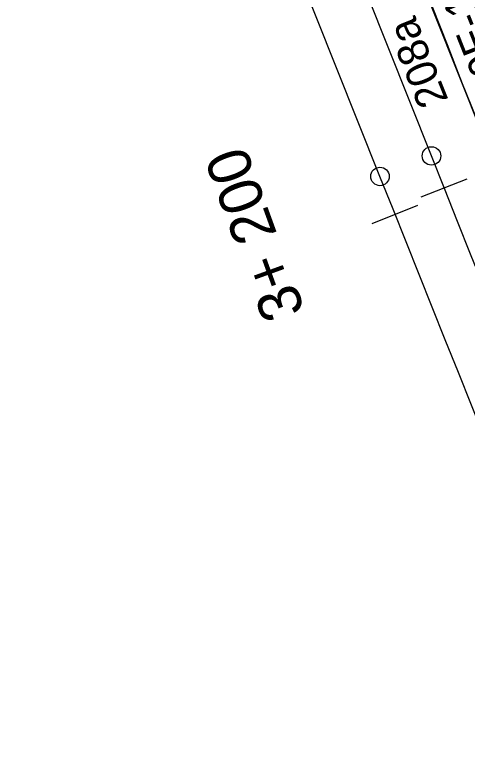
# Model space of a CAD drawing. Extents: x 149855 to 151460, y 6580726 to 6583068.
# Drawn here: x 150983.5 to 151020.2, y 6581433.2 to 6581493.4 of the extents above; entities that cross this region are included whole.
import ezdxf

# ---------------------------------------------------------------- set-up
doc = ezdxf.new("R2010")
doc.units = 0
for name, color, linetype in [('Hektometer L', 7, 'Continuous'), ('Hektometer T', 7, 'Continuous'), ('Spårmitt L', 7, 'Continuous'), ('Tp bef behålls P', 7, 'Continuous'), ('Växel L', 7, 'Continuous'), ('Växelnummer T', 7, 'Continuous'), ('Växeltyp T', 7, 'Continuous')]:
    doc.layers.add(name, color=color, linetype=linetype)

msp = doc.modelspace()

# ---------------------------------------------------------------- linework, layer by layer
at = {"layer": 'Hektometer L'}
for points in [[(151016.511, 6581478.609), (151020.226, 6581480.091)], [(151012.52, 6581476.468), (151016.235, 6581477.95)]]:
    msp.add_lwpolyline(points, dxfattribs=at)
at = {"layer": 'Spårmitt L'}
for points in [[(151021.567, 6581483.477), (150991.892, 6581557.911)], [(151017.336, 6581481.94), (150987.713, 6581556.243)], [(151013.156, 6581480.274), (150983.533, 6581554.575)], [(151037.777, 6581431.651), (151036.669, 6581434.284), (151035.565, 6581436.92), (151034.467, 6581439.558), (151033.373, 6581442.197), (151032.284, 6581444.838), (151031.199, 6581447.482), (151030.118, 6581450.126), (151029.04, 6581452.772), (151027.966, 6581455.42), (151026.895, 6581458.068), (151025.826, 6581460.718), (151024.759, 6581463.369), (151023.695, 6581466.02), (151022.632, 6581468.672), (151021.571, 6581471.325), (151020.511, 6581473.978), (151019.452, 6581476.632), (151018.394, 6581479.286), (151017.336, 6581481.94)], [(151032.487, 6581432.617), (151031.384, 6581435.253), (151030.286, 6581437.891), (151029.193, 6581440.53), (151028.104, 6581443.172), (151027.019, 6581445.815), (151025.938, 6581448.46), (151024.86, 6581451.106), (151023.786, 6581453.753), (151022.714, 6581456.402), (151021.646, 6581459.052), (151020.579, 6581461.702), (151019.515, 6581464.354), (151018.452, 6581467.006), (151017.391, 6581469.659), (151016.331, 6581472.312), (151015.272, 6581474.966), (151014.214, 6581477.619), (151013.156, 6581480.273)]]:
    msp.add_lwpolyline(points, dxfattribs=at)
at = {"layer": 'Tp bef behålls P'}
for centre in [(151017.336, 6581481.94), (151013.156, 6581480.274)]:
    msp.add_circle(centre, 0.75, dxfattribs=at)
at = {"layer": 'Växel L'}
for p, q in [((151017.618, 6581493.383), (151017.655, 6581493.383)), ((151017.626, 6581493.363), (151017.663, 6581493.363)), ((151017.634, 6581493.343), (151017.671, 6581493.343)), ((151017.642, 6581493.323), (151017.679, 6581493.323)), ((151017.65, 6581493.303), (151017.687, 6581493.303)), ((151017.658, 6581493.283), (151017.695, 6581493.283)), ((151017.666, 6581493.263), (151017.702, 6581493.263)), ((151017.674, 6581493.243), (151017.71, 6581493.243)), ((151017.682, 6581493.223), (151017.718, 6581493.223)), ((151017.69, 6581493.203), (151017.726, 6581493.203)), ((151017.698, 6581493.183), (151017.734, 6581493.183)), ((151017.706, 6581493.163), (151017.741, 6581493.163)), ((151017.714, 6581493.143), (151017.749, 6581493.143)), ((151017.722, 6581493.123), (151017.757, 6581493.123)), ((151017.729, 6581493.103), (151017.765, 6581493.103)), ((151017.737, 6581493.083), (151017.773, 6581493.083)), ((151017.745, 6581493.063), (151017.781, 6581493.063)), ((151017.753, 6581493.043), (151017.788, 6581493.043)), ((151017.761, 6581493.023), (151017.796, 6581493.023)), ((151017.769, 6581493.003), (151017.804, 6581493.003)), ((151017.777, 6581492.983), (151017.812, 6581492.983)), ((151017.785, 6581492.963), (151017.82, 6581492.963)), ((151017.793, 6581492.943), (151017.827, 6581492.943)), ((151017.801, 6581492.923), (151017.835, 6581492.923)), ((151017.809, 6581492.903), (151017.843, 6581492.903)), ((151017.817, 6581492.883), (151017.851, 6581492.883)), ((151017.825, 6581492.863), (151017.859, 6581492.863)), ((151017.833, 6581492.843), (151017.867, 6581492.843)), ((151017.841, 6581492.823), (151017.874, 6581492.823)), ((151017.849, 6581492.803), (151017.882, 6581492.803)), ((151017.857, 6581492.783), (151017.89, 6581492.783)), ((151017.865, 6581492.763), (151017.898, 6581492.763)), ((151017.873, 6581492.743), (151017.906, 6581492.743)), ((151017.881, 6581492.723), (151017.913, 6581492.723)), ((151017.889, 6581492.703), (151017.921, 6581492.703)), ((151017.897, 6581492.683), (151017.929, 6581492.683)), ((151017.905, 6581492.663), (151017.937, 6581492.663)), ((151017.913, 6581492.643), (151017.945, 6581492.643)), ((151017.921, 6581492.623), (151017.953, 6581492.623)), ((151017.929, 6581492.603), (151017.96, 6581492.603)), ((151017.937, 6581492.583), (151017.968, 6581492.583)), ((151017.945, 6581492.563), (151017.976, 6581492.563)), ((151017.953, 6581492.543), (151017.984, 6581492.543)), ((151017.961, 6581492.523), (151017.992, 6581492.523)), ((151017.969, 6581492.503), (151017.999, 6581492.503)), ((151017.977, 6581492.483), (151018.007, 6581492.483)), ((151017.985, 6581492.463), (151018.015, 6581492.463)), ((151017.993, 6581492.443), (151018.023, 6581492.443)), ((151018.001, 6581492.423), (151018.031, 6581492.423)), ((151018.009, 6581492.403), (151018.039, 6581492.403)), ((151018.017, 6581492.383), (151018.046, 6581492.383)), ((151018.024, 6581492.363), (151018.054, 6581492.363)), ((151018.032, 6581492.343), (151018.062, 6581492.343)), ((151018.04, 6581492.323), (151018.07, 6581492.323)), ((151018.048, 6581492.303), (151018.078, 6581492.303)), ((151018.056, 6581492.283), (151018.085, 6581492.283)), ((151018.064, 6581492.263), (151018.093, 6581492.263)), ((151018.072, 6581492.243), (151018.101, 6581492.243)), ((151018.08, 6581492.223), (151018.109, 6581492.223)), ((151018.088, 6581492.203), (151018.117, 6581492.203)), ((151018.096, 6581492.183), (151018.125, 6581492.183)), ((151018.104, 6581492.163), (151018.132, 6581492.163)), ((151018.112, 6581492.143), (151018.14, 6581492.143)), ((151018.12, 6581492.123), (151018.148, 6581492.123)), ((151018.128, 6581492.103), (151018.156, 6581492.103)), ((151018.136, 6581492.083), (151018.164, 6581492.083)), ((151018.144, 6581492.063), (151018.171, 6581492.063)), ((151018.152, 6581492.043), (151018.179, 6581492.043)), ((151018.16, 6581492.023), (151018.187, 6581492.023)), ((151018.168, 6581492.003), (151018.195, 6581492.003)), ((151018.176, 6581491.983), (151018.203, 6581491.983)), ((151018.184, 6581491.963), (151018.211, 6581491.963)), ((151018.192, 6581491.943), (151018.218, 6581491.943)), ((151018.2, 6581491.923), (151018.226, 6581491.923)), ((151018.208, 6581491.903), (151018.234, 6581491.903)), ((151018.216, 6581491.883), (151018.242, 6581491.883)), ((151018.224, 6581491.863), (151018.25, 6581491.863)), ((151018.232, 6581491.843), (151018.257, 6581491.843)), ((151018.24, 6581491.823), (151018.265, 6581491.823)), ((151018.248, 6581491.803), (151018.273, 6581491.803)), ((151018.256, 6581491.783), (151018.281, 6581491.783)), ((151018.264, 6581491.763), (151018.289, 6581491.763)), ((151018.272, 6581491.743), (151018.297, 6581491.743)), ((151018.28, 6581491.723), (151018.304, 6581491.723)), ((151018.288, 6581491.703), (151018.312, 6581491.703)), ((151018.296, 6581491.683), (151018.32, 6581491.683)), ((151018.304, 6581491.663), (151018.328, 6581491.663)), ((151018.312, 6581491.643), (151018.336, 6581491.643)), ((151018.32, 6581491.623), (151018.343, 6581491.623)), ((151018.327, 6581491.603), (151018.351, 6581491.603)), ((151018.335, 6581491.583), (151018.359, 6581491.583)), ((151018.343, 6581491.563), (151018.367, 6581491.563)), ((151018.351, 6581491.543), (151018.375, 6581491.543)), ((151018.359, 6581491.523), (151018.382, 6581491.523)), ((151018.367, 6581491.503), (151018.39, 6581491.503)), ((151018.375, 6581491.483), (151018.398, 6581491.483)), ((151018.383, 6581491.463), (151018.406, 6581491.463)), ((151018.391, 6581491.443), (151018.414, 6581491.443)), ((151018.399, 6581491.423), (151018.422, 6581491.423)), ((151018.407, 6581491.403), (151018.429, 6581491.403)), ((151018.415, 6581491.383), (151018.437, 6581491.383)), ((151018.423, 6581491.363), (151018.445, 6581491.363)), ((151018.431, 6581491.343), (151018.453, 6581491.343)), ((151018.439, 6581491.323), (151018.461, 6581491.323)), ((151018.447, 6581491.303), (151018.468, 6581491.303)), ((151018.455, 6581491.283), (151018.476, 6581491.283)), ((151018.463, 6581491.263), (151018.484, 6581491.263)), ((151018.471, 6581491.243), (151018.492, 6581491.243)), ((151018.479, 6581491.223), (151018.5, 6581491.223)), ((151018.487, 6581491.203), (151018.508, 6581491.203)), ((151018.495, 6581491.183), (151018.515, 6581491.183)), ((151018.503, 6581491.163), (151018.523, 6581491.163)), ((151018.511, 6581491.143), (151018.531, 6581491.143)), ((151018.519, 6581491.123), (151018.539, 6581491.123)), ((151018.527, 6581491.103), (151018.547, 6581491.103)), ((151018.535, 6581491.083), (151018.554, 6581491.083)), ((151018.543, 6581491.063), (151018.562, 6581491.063)), ((151018.551, 6581491.043), (151018.57, 6581491.043)), ((151018.559, 6581491.023), (151018.578, 6581491.023)), ((151018.567, 6581491.003), (151018.586, 6581491.003)), ((151018.575, 6581490.983), (151018.594, 6581490.983)), ((151018.583, 6581490.963), (151018.601, 6581490.963)), ((151018.591, 6581490.943), (151018.609, 6581490.943)), ((151018.599, 6581490.923), (151018.617, 6581490.923)), ((151018.607, 6581490.903), (151018.625, 6581490.903)), ((151018.615, 6581490.883), (151018.633, 6581490.883)), ((151018.623, 6581490.863), (151018.641, 6581490.863)), ((151018.63, 6581490.843), (151018.649, 6581490.843)), ((151018.638, 6581490.823), (151018.657, 6581490.823)), ((151018.646, 6581490.803), (151018.664, 6581490.803)), ((151018.654, 6581490.783), (151018.672, 6581490.783)), ((151018.662, 6581490.763), (151018.68, 6581490.763)), ((151018.67, 6581490.743), (151018.688, 6581490.743)), ((151018.678, 6581490.723), (151018.696, 6581490.723)), ((151018.686, 6581490.703), (151018.704, 6581490.703)), ((151018.694, 6581490.683), (151018.712, 6581490.683)), ((151018.702, 6581490.663), (151018.72, 6581490.663)), ((151018.71, 6581490.643), (151018.728, 6581490.643)), ((151018.718, 6581490.623), (151018.735, 6581490.623)), ((151018.726, 6581490.603), (151018.743, 6581490.603)), ((151018.734, 6581490.583), (151018.751, 6581490.583)), ((151018.742, 6581490.563), (151018.759, 6581490.563)), ((151018.75, 6581490.543), (151018.767, 6581490.543)), ((151018.758, 6581490.523), (151018.775, 6581490.523)), ((151018.766, 6581490.503), (151018.783, 6581490.503)), ((151018.774, 6581490.483), (151018.791, 6581490.483)), ((151018.782, 6581490.463), (151018.798, 6581490.463)), ((151018.79, 6581490.443), (151018.806, 6581490.443)), ((151018.798, 6581490.423), (151018.814, 6581490.423)), ((151018.806, 6581490.403), (151018.822, 6581490.403)), ((151018.814, 6581490.383), (151018.83, 6581490.383)), ((151018.822, 6581490.363), (151018.838, 6581490.363)), ((151018.83, 6581490.343), (151018.846, 6581490.343)), ((151018.838, 6581490.323), (151018.854, 6581490.323)), ((151018.846, 6581490.303), (151018.861, 6581490.303)), ((151018.854, 6581490.283), (151018.869, 6581490.283)), ((151018.862, 6581490.263), (151018.877, 6581490.263)), ((151018.87, 6581490.243), (151018.885, 6581490.243)), ((151018.878, 6581490.223), (151018.893, 6581490.223)), ((151018.886, 6581490.203), (151018.901, 6581490.203)), ((151018.894, 6581490.183), (151018.909, 6581490.183)), ((151018.902, 6581490.163), (151018.917, 6581490.163)), ((151018.91, 6581490.143), (151018.924, 6581490.143)), ((151018.918, 6581490.123), (151018.932, 6581490.123)), ((151018.926, 6581490.103), (151018.94, 6581490.103)), ((151018.933, 6581490.083), (151018.948, 6581490.083)), ((151018.941, 6581490.063), (151018.956, 6581490.063)), ((151018.949, 6581490.043), (151018.964, 6581490.043)), ((151018.957, 6581490.023), (151018.972, 6581490.023)), ((151018.965, 6581490.003), (151018.98, 6581490.003)), ((151018.973, 6581489.983), (151018.988, 6581489.983)), ((151018.981, 6581489.963), (151018.995, 6581489.963)), ((151018.989, 6581489.943), (151019.003, 6581489.943)), ((151018.997, 6581489.923), (151019.011, 6581489.923)), ((151019.005, 6581489.903), (151019.019, 6581489.903)), ((151019.013, 6581489.883), (151019.027, 6581489.883)), ((151019.021, 6581489.863), (151019.035, 6581489.863)), ((151019.029, 6581489.843), (151019.043, 6581489.843)), ((151019.037, 6581489.823), (151019.051, 6581489.823)), ((151019.045, 6581489.803), (151019.058, 6581489.803)), ((151019.053, 6581489.783), (151019.066, 6581489.783)), ((151019.061, 6581489.763), (151019.074, 6581489.763)), ((151019.069, 6581489.743), (151019.082, 6581489.743)), ((151019.077, 6581489.723), (151019.09, 6581489.723)), ((151019.085, 6581489.703), (151019.098, 6581489.703)), ((151019.093, 6581489.683), (151019.106, 6581489.683)), ((151019.101, 6581489.663), (151019.114, 6581489.663)), ((151019.109, 6581489.643), (151019.121, 6581489.643)), ((151019.117, 6581489.623), (151019.129, 6581489.623)), ((151019.125, 6581489.603), (151019.137, 6581489.603)), ((151019.133, 6581489.583), (151019.145, 6581489.583)), ((151019.141, 6581489.563), (151019.153, 6581489.563)), ((151019.149, 6581489.543), (151019.161, 6581489.543)), ((151019.157, 6581489.523), (151019.169, 6581489.523)), ((151019.165, 6581489.503), (151019.177, 6581489.503)), ((151019.173, 6581489.483), (151019.185, 6581489.483)), ((151019.181, 6581489.463), (151019.192, 6581489.463)), ((151019.189, 6581489.443), (151019.2, 6581489.443)), ((151019.197, 6581489.423), (151019.208, 6581489.423)), ((151019.205, 6581489.403), (151019.216, 6581489.403)), ((151019.213, 6581489.383), (151019.224, 6581489.383)), ((151019.221, 6581489.363), (151019.232, 6581489.363)), ((151019.229, 6581489.343), (151019.24, 6581489.343)), ((151019.236, 6581489.323), (151019.248, 6581489.323)), ((151019.244, 6581489.303), (151019.255, 6581489.303)), ((151019.252, 6581489.283), (151019.263, 6581489.283)), ((151019.26, 6581489.263), (151019.271, 6581489.263)), ((151019.268, 6581489.243), (151019.279, 6581489.243)), ((151019.276, 6581489.223), (151019.287, 6581489.223)), ((151019.284, 6581489.203), (151019.295, 6581489.203)), ((151019.292, 6581489.183), (151019.303, 6581489.183)), ((151019.3, 6581489.163), (151019.311, 6581489.163)), ((151019.308, 6581489.143), (151019.318, 6581489.143)), ((151019.316, 6581489.123), (151019.326, 6581489.123)), ((151019.324, 6581489.103), (151019.334, 6581489.103)), ((151019.332, 6581489.083), (151019.342, 6581489.083)), ((151019.34, 6581489.063), (151019.35, 6581489.063)), ((151019.348, 6581489.043), (151019.358, 6581489.043)), ((151019.356, 6581489.023), (151019.366, 6581489.023)), ((151019.364, 6581489.003), (151019.374, 6581489.003)), ((151019.372, 6581488.983), (151019.382, 6581488.983)), ((151019.38, 6581488.963), (151019.389, 6581488.963)), ((151019.388, 6581488.943), (151019.397, 6581488.943)), ((151019.396, 6581488.923), (151019.405, 6581488.923)), ((151019.404, 6581488.903), (151019.413, 6581488.903)), ((151019.412, 6581488.883), (151019.421, 6581488.883)), ((151019.42, 6581488.863), (151019.429, 6581488.863)), ((151019.428, 6581488.843), (151019.437, 6581488.843)), ((151019.436, 6581488.823), (151019.445, 6581488.823)), ((151019.444, 6581488.803), (151019.452, 6581488.803)), ((151019.452, 6581488.783), (151019.46, 6581488.783)), ((151019.46, 6581488.763), (151019.468, 6581488.763)), ((151019.468, 6581488.743), (151019.476, 6581488.743)), ((151019.476, 6581488.723), (151019.484, 6581488.723)), ((151019.484, 6581488.703), (151019.492, 6581488.703)), ((151019.492, 6581488.683), (151019.5, 6581488.683)), ((151019.5, 6581488.663), (151019.508, 6581488.663)), ((151019.508, 6581488.643), (151019.515, 6581488.643)), ((151019.516, 6581488.623), (151019.523, 6581488.623)), ((151019.524, 6581488.603), (151019.531, 6581488.603)), ((151019.531, 6581488.583), (151019.539, 6581488.583)), ((151019.539, 6581488.563), (151019.547, 6581488.563)), ((151019.547, 6581488.543), (151019.555, 6581488.543)), ((151019.555, 6581488.523), (151019.563, 6581488.523)), ((151019.563, 6581488.503), (151019.571, 6581488.503)), ((151019.571, 6581488.483), (151019.579, 6581488.483)), ((151019.579, 6581488.463), (151019.586, 6581488.463)), ((151019.587, 6581488.443), (151019.594, 6581488.443)), ((151019.595, 6581488.423), (151019.602, 6581488.423)), ((151019.603, 6581488.403), (151019.61, 6581488.403)), ((151019.611, 6581488.383), (151019.618, 6581488.383)), ((151019.619, 6581488.363), (151019.626, 6581488.363)), ((151019.627, 6581488.343), (151019.634, 6581488.343)), ((151019.635, 6581488.323), (151019.642, 6581488.323)), ((151019.643, 6581488.303), (151019.649, 6581488.303)), ((151019.651, 6581488.283), (151019.657, 6581488.283)), ((151019.659, 6581488.263), (151019.665, 6581488.263)), ((151019.667, 6581488.243), (151019.673, 6581488.243)), ((151019.675, 6581488.223), (151019.681, 6581488.223)), ((151019.683, 6581488.203), (151019.689, 6581488.203)), ((151019.691, 6581488.183), (151019.697, 6581488.183)), ((151019.699, 6581488.163), (151019.705, 6581488.163)), ((151019.707, 6581488.143), (151019.712, 6581488.143)), ((151019.715, 6581488.123), (151019.72, 6581488.123)), ((151019.723, 6581488.103), (151019.728, 6581488.103)), ((151019.731, 6581488.083), (151019.736, 6581488.083)), ((151019.739, 6581488.063), (151019.744, 6581488.063)), ((151019.747, 6581488.043), (151019.752, 6581488.043)), ((151019.755, 6581488.023), (151019.76, 6581488.023)), ((151019.763, 6581488.003), (151019.768, 6581488.003)), ((151019.771, 6581487.983), (151019.776, 6581487.983)), ((151019.779, 6581487.963), (151019.783, 6581487.963)), ((151019.787, 6581487.943), (151019.791, 6581487.943)), ((151019.795, 6581487.923), (151019.799, 6581487.923)), ((151019.803, 6581487.903), (151019.807, 6581487.903)), ((151019.811, 6581487.883), (151019.815, 6581487.883)), ((151019.819, 6581487.863), (151019.823, 6581487.863)), ((151019.827, 6581487.843), (151019.831, 6581487.843)), ((151019.834, 6581487.823), (151019.839, 6581487.823)), ((151019.842, 6581487.803), (151019.847, 6581487.803)), ((151019.85, 6581487.783), (151019.855, 6581487.783)), ((151019.858, 6581487.763), (151019.863, 6581487.763)), ((151019.866, 6581487.743), (151019.871, 6581487.743)), ((151019.874, 6581487.723), (151019.879, 6581487.723)), ((151019.882, 6581487.703), (151019.887, 6581487.703)), ((151019.89, 6581487.683), (151019.895, 6581487.683)), ((151019.898, 6581487.663), (151019.903, 6581487.663)), ((151019.906, 6581487.643), (151019.91, 6581487.643)), ((151019.914, 6581487.623), (151019.918, 6581487.623)), ((151019.922, 6581487.603), (151019.926, 6581487.603)), ((151019.93, 6581487.583), (151019.934, 6581487.583)), ((151019.938, 6581487.563), (151019.942, 6581487.563)), ((151019.946, 6581487.543), (151019.95, 6581487.543)), ((151019.954, 6581487.523), (151019.958, 6581487.523)), ((151019.962, 6581487.503), (151019.966, 6581487.503)), ((151019.97, 6581487.483), (151019.974, 6581487.483)), ((151019.978, 6581487.463), (151019.982, 6581487.463)), ((151019.986, 6581487.443), (151019.99, 6581487.443)), ((151019.994, 6581487.423), (151019.998, 6581487.423)), ((151020.002, 6581487.403), (151020.006, 6581487.403)), ((151020.01, 6581487.383), (151020.014, 6581487.383)), ((151020.018, 6581487.363), (151020.022, 6581487.363)), ((151020.026, 6581487.343), (151020.03, 6581487.343)), ((151020.034, 6581487.323), (151020.038, 6581487.323)), ((151020.042, 6581487.303), (151020.045, 6581487.303)), ((151020.05, 6581487.283), (151020.053, 6581487.283)), ((151020.058, 6581487.263), (151020.061, 6581487.263)), ((151020.066, 6581487.243), (151020.069, 6581487.243)), ((151020.074, 6581487.223), (151020.077, 6581487.223)), ((151020.082, 6581487.203), (151020.085, 6581487.203)), ((151020.09, 6581487.183), (151020.093, 6581487.183)), ((151020.098, 6581487.163), (151020.101, 6581487.163)), ((151020.106, 6581487.143), (151020.109, 6581487.143)), ((151020.114, 6581487.123), (151020.117, 6581487.123)), ((151020.122, 6581487.103), (151020.125, 6581487.103)), ((151020.13, 6581487.083), (151020.133, 6581487.083)), ((151020.137, 6581487.063), (151020.141, 6581487.063)), ((151020.145, 6581487.043), (151020.149, 6581487.043)), ((151020.153, 6581487.023), (151020.157, 6581487.023)), ((151020.161, 6581487.003), (151020.165, 6581487.003)), ((151020.169, 6581486.983), (151020.173, 6581486.983)), ((151020.177, 6581486.963), (151020.181, 6581486.963)), ((151020.185, 6581486.943), (151020.188, 6581486.943)), ((151020.193, 6581486.923), (151020.196, 6581486.923)), ((151020.201, 6581486.903), (151020.204, 6581486.903)), ((151020.209, 6581486.883), (151020.212, 6581486.883)), ((151020.217, 6581486.863), (151020.22, 6581486.863)), ((151020.225, 6581486.843), (151020.228, 6581486.843))]:
    msp.add_line(p, q, dxfattribs=at)
msp.add_lwpolyline([(151020.98, 6581484.949), (150996.976, 6581545.158), (150998.619, 6581545.762), (150999.659, 6581542.693), (151000.707, 6581539.627), (151001.763, 6581536.564), (151002.828, 6581533.504), (151003.901, 6581530.447), (151004.982, 6581527.392), (151006.071, 6581524.341), (151007.169, 6581521.292), (151008.275, 6581518.247), (151009.389, 6581515.204), (151010.511, 6581512.165), (151011.642, 6581509.128), (151012.781, 6581506.095), (151013.927, 6581503.065), (151015.083, 6581500.037), (151016.246, 6581497.013), (151017.417, 6581493.992), (151018.597, 6581490.975), (151019.784, 6581487.96)], close=True, dxfattribs=at)

# ---------------------------------------------------------------- texts
at = {"layer": 'Hektometer T'}
msp.add_text('3+ 200', height=3.5, rotation=109.97857, dxfattribs=at).set_placement((151007.105, 6581469.347))
at = {"layer": 'Växelnummer T'}
msp.add_text('208a', height=2.5, rotation=111.67826, dxfattribs=at).set_placement((151018.732, 6581486.479))
at = {"layer": 'Växeltyp T'}
msp.add_text('60E-1:18.5', height=2.5, rotation=111.67826, dxfattribs=at).set_placement((151023.769, 6581487.281))

doc.saveas('drawing.dxf')
